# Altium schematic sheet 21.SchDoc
size 337 x 236 mm
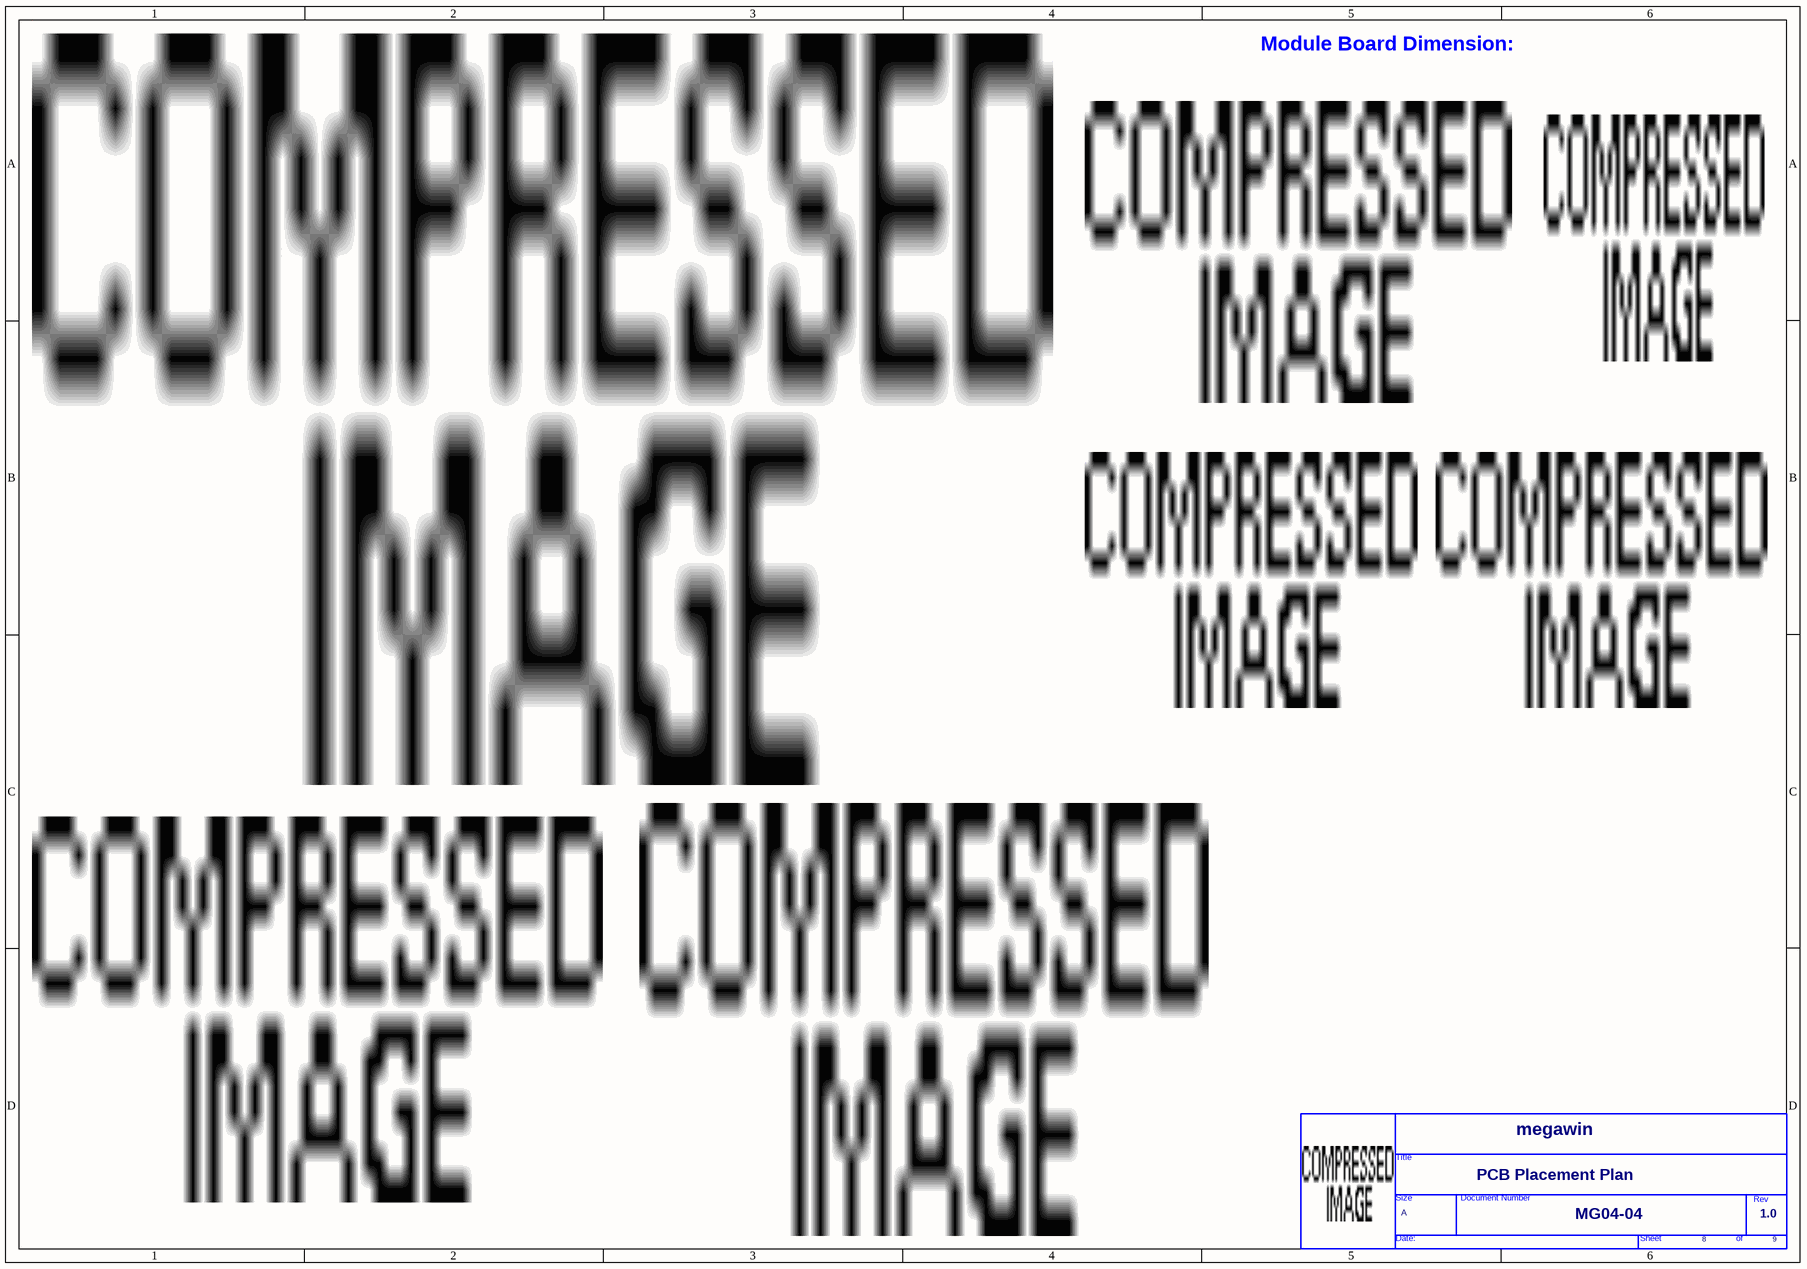
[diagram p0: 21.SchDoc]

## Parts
*  OrgName: megawin  Doc: MG04-04  RevCode: 1.0  Title: PCB Placement Plan  Page Size: A  Page Number: 8  Page Count: 9  (hidden comment: TitleBlock_MegaWin)  (graphical)

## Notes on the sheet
- Module Board Dimension:
